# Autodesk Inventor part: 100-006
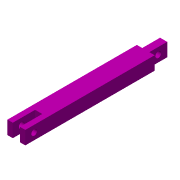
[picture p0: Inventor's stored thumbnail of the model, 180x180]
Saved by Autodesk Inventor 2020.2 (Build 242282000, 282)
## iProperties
Created: 2014-01
Part Number: 100-006
Material: Ogólny
Document SubType Name: Modeling
Designer: F.Stasiak
Density: 1 g/cm^3
Appearance: Fioletowe
Manager: www.cadconsulting.pl
Company: Fabian Stasiak CAD Consulting
Author: F.Stasiak
Subject: Zbiór ćwiczeń. Autodesk Inventor 2020. Kurs podstawowy
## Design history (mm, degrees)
sketch "Szkic1"
  geometry: L1 (-10, 7.5)-(10, 7.5); L2 (10, 7.5)-(10, -7.5); L3 (10, -7.5)-(-10, -7.5); L4 (-10, -7.5)-(-10, 7.5); L5 (-10, 7.5)-(10, -7.5); L6 (10, 7.5)-(-10, -7.5); 1 further point
  constraints: 12 end point, 2 midpoint, 2 parallel, 1 horizontal, 1 perpendicular
  dimensions: "d0" = 20 distance of L2.end L3.end; "d1" = 15 distance of L1.end L2.end
extrude "Wyciągnięcie proste1" new body sketch "Szkic1" distance "d2" = 120; taper "d3" = 0 deg
sketch "Szkic2"
  geometry: L1 (10, 7.5)-(-10, 7.5) reference; L2 (-10, 7.5)-(-10, -7.5) reference; L3 (-10, -7.5)-(10, -7.5) reference; L4 (10, -7.5)-(10, 7.5) reference; L5 (-4, 7.5)-(-4, -7.5); L6 (4, -7.5)-(4, 7.5); L7 (-4, 0)-(4, 0); 2 further points
  constraints: 6 end point, 4 point on line, 3 midpoint, 2 perpendicular, 1 coincident
  dimensions: "d4" = 8 distance between parallel lines of L6 L5
extrude "Wyciągnięcie proste2" join sketch "Szkic2" distance "d5" = 25; taper "d6" = 0 deg
sketch "Szkic3"
  geometry: L1 (-145, 0)-(-145, 15) reference; 3 further points
  constraints: 1 horizontal alignment, 1 midpoint
  dimensions: "d7" = 10 distance from line of point (-135, 7.5) L1
hole "Otwór1" sketch "Szkic3" at (-135, 7.5) diameter "d8" = 6.5; stored, may be unused: countersink angle "d12" = 90 deg, drill point angle "d14" = 118 deg; dims "d9" = 6, "d10" = 4, "d11" = 2, "d13" = 8
sketch "Szkic4"
  geometry: L1 (10, 7.5)-(-10, 7.5) reference; L2 (-10, -7.5)-(10, -7.5) reference; L3 (4, -7.5)-(4, 7.5) reference; L4 (-4, 7.5)-(-4, -7.5) reference; 1 further point
extrude "Wyciągnięcie proste3" join sketch "Szkic4" distance "d15" = 20; taper "d16" = 0 deg
sketch "Szkic5"
  geometry: L1 (-100, 15)-(-100, 0) reference; 2 further points
  constraints: 1 horizontal alignment, 1 midpoint
  dimensions: "d25" = 10 distance from line of L1 point (-110, 7.5)
hole "Otwór2" sketch "Szkic5" at (-110, 7.5) diameter "d24" = 6.5; stored, may be unused: drill point angle "d19" = 118 deg, countersink angle "d20" = 90 deg; dims "d17" = 6, "d21" = 2, "d22" = 4, "d23" = 8
node "Bryła1"
